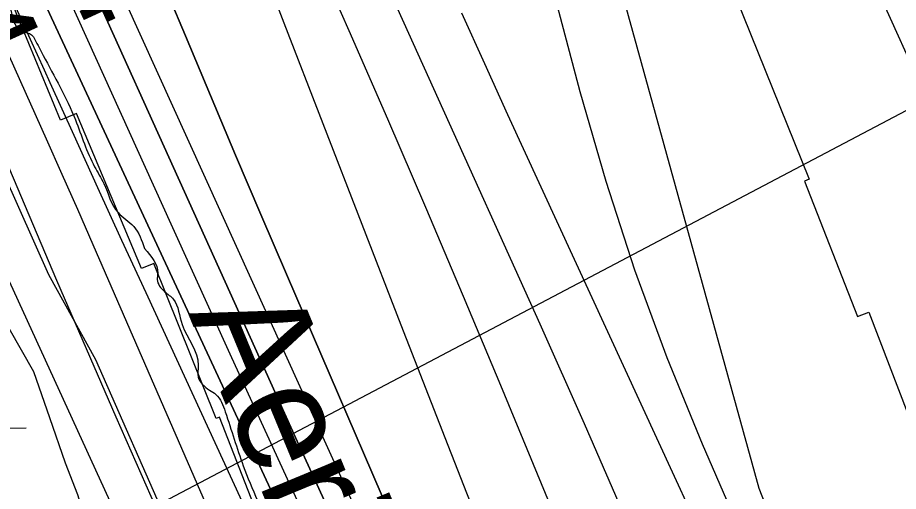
# Model space of a CAD drawing. Extents: x 3424494 to 3462436, y 522220 to 547718.
# Drawn here: x 3439589 to 3440243, y 541201 to 541553 of the extents above; entities that cross this region are included whole.
import ezdxf

# ---------------------------------------------------------------- set-up
doc = ezdxf.new("R2010")
doc.units = 0
for name, color, linetype in [('V-RIVR-EDGE', 7, 'Continuous'), ('V-RIVR-IDEN', 7, 'Continuous'), ('V-RIVR-RANG', 7, 'Continuous'), ('V-RRAP-RVMT', 7, 'Continuous'), ('V-SITE-VEGE', 7, 'Continuous'), ('V-TOPO-DPTH', 7, 'Continuous'), ('V-TOPO-MAJR', 7, 'Continuous'), ('V-TOPO-MINR', 7, 'Continuous'), ('V-TOPO-WATR', 7, 'Continuous'), ('V-WETL-SWMP', 7, 'Continuous')]:
    doc.layers.add(name, color=color, linetype=linetype)

msp = doc.modelspace()

# ---------------------------------------------------------------- linework, layer by layer
at = {"layer": 'V-RIVR-EDGE'}
for points in [[(3438393.42, 545837.57), (3438393.61, 545836.87), (3438395.05, 545831.39), (3438401.62, 545826.62), (3438403.8, 545821.13), (3438403.78, 545813.45), (3438405.22, 545801.75), (3438408.47, 545786.39), (3438409.18, 545777.98), (3438409.16, 545769.94), (3438409.49, 545757.14), (3438410.92, 545744.71), (3438420.29, 545688.76), (3438423.49, 545652.93), (3438428.86, 545606.12), (3438430.6, 545570.3), (3438432.37, 545549.09), (3438435.92, 545504.12), (3438439.16, 545485.47), (3438444.96, 545463.89), (3438449.31, 545451.81), (3438457.7, 545444.12), (3438458.06, 545439), (3438458.77, 545433.15), (3438463.52, 545430.21), (3438470.82, 545426.9), (3438472.63, 545421.41), (3438472.25, 545413.01), (3438471.11, 545394.73), (3438468.15, 545380.85), (3438467.77, 545375.37), (3438465.55, 545364.41), (3438464.78, 545351.25), (3438465.85, 545339.91), (3438471.67, 545328.93), (3438480.75, 545301.86), (3438480.71, 545287.24), (3438482.14, 545273.71), (3438487.22, 545257.98), (3438494.14, 545246.99), (3438498.87, 545239.31), (3438502.86, 545227.23), (3438508.27, 545196.51), (3438511.14, 545174.21), (3438523.44, 545123), (3438525.59, 545104.72), (3438525.57, 545098.14), (3438527.72, 545082.41), (3438530.97, 545064.86), (3438530.94, 545051.33), (3438530.54, 545038.91), (3438527.6, 545030.87), (3438526.84, 545021), (3438528.62, 545002.72), (3438527.46, 544975.67), (3438526.31, 544955.57), (3438524.81, 544938.76), (3438526.99, 544931.81), (3438537.92, 544918.26), (3438543.74, 544908.37), (3438545.55, 544899.23), (3438545.53, 544889.73), (3438542.56, 544875.11), (3438542.17, 544862.68), (3438543.62, 544857.2), (3438543.61, 544855), (3438540.68, 544850.62), (3438539.19, 544841.12), (3438540.25, 544827.23), (3438541.69, 544817.72), (3438544.95, 544805.29), (3438544.91, 544790.3), (3438543.39, 544767.27), (3438545.9, 544746.43), (3438547.7, 544732.9), (3438549.12, 544719.01), (3438553.49, 544712.42), (3438557.51, 544708.38), (3438557.13, 544706.19), (3438556.03, 544704.37), (3438550.91, 544701.46), (3438550.16, 544693.78), (3438554.49, 544672.57), (3438557.73, 544650.63), (3438563.14, 544620.27), (3438569.66, 544598.69), (3438581.95, 544543.1), (3438585.19, 544522.98), (3438584.79, 544506.53), (3438588.41, 544491.17), (3438594.94, 544472.51), (3438598.56, 544458.98), (3438598.51, 544439.6), (3438598.48, 544424.98), (3438598.08, 544411.82), (3438598.06, 544405.61), (3438599.51, 544397.56), (3438604.22, 544381.1), (3438610.37, 544356.96), (3438613.26, 544341.6), (3438619.09, 544333.18), (3438624.91, 544321.1), (3438628.15, 544301.72), (3438628.82, 544279.42), (3438634.99, 544260.03), (3438634.97, 544251.26), (3438637.85, 544233.34), (3438638.54, 544216.16), (3438645.09, 544204.08), (3438650.91, 544193.1), (3438650.88, 544182.13), (3438651.56, 544159.1), (3438651.54, 544153.25), (3438652.96, 544137.53), (3438657.32, 544123.99), (3438667.11, 544092.89), (3438672.9, 544069.49), (3438679.8, 544048.63), (3438680.49, 544035.47), (3438681.93, 544024.5), (3438680.45, 544017.19), (3438685.53, 544000.73), (3438686.94, 543981.72), (3438692.73, 543957.58), (3438693.77, 543933.08), (3438694.09, 543918.1), (3438698.07, 543900.54), (3438698.41, 543889.94), (3438698.4, 543885.55), (3438700.96, 543885.18), (3438708.64, 543887.72), (3438712.65, 543882.59), (3438718.45, 543864.67), (3438733.33, 543818.2), (3438741.31, 543793.69), (3438746.73, 543767.36), (3438753.96, 543734.08), (3438762.28, 543698.96), (3438770.98, 543671.53), (3438780.05, 543642.62), (3438782.94, 543630.92), (3438781.85, 543630.92), (3438771.24, 543630.22), (3438766.85, 543628.77), (3438765.74, 543622.56), (3438771.21, 543615.23), (3438777.02, 543602.42), (3438775.17, 543590), (3438778.8, 543582.31), (3438781.72, 543581.21), (3438785.75, 543582.3), (3438793.07, 543586.3), (3438797.82, 543584.82), (3438800.36, 543578.24), (3438805.76, 543546.06), (3438811.93, 543525.94), (3438819.53, 543497.04), (3438822.81, 543490.09), (3438824.62, 543484.96), (3438830.07, 543471.42), (3438839.89, 543450.93), (3438843.89, 543441.78), (3438850.42, 543423.85), (3438851.87, 543417.27), (3438850.75, 543408.13), (3438850.37, 543400.82), (3438855.08, 543386.19), (3438860.17, 543372.29), (3438866.73, 543366.06), (3438867.8, 543356.55), (3438867.78, 543347.78), (3438868.86, 543341.19), (3438880.52, 543326.91), (3438889.63, 543312.99), (3438898.72, 543293.96), (3438901.98, 543280.06), (3438905.96, 543265.07), (3438917.2, 543229.58), (3438923, 543209.46), (3438927.74, 543203.6), (3438932.81, 543185.68), (3438937.14, 543160.81), (3438942.56, 543134.84), (3438946.9, 543117.65), (3438946.88, 543110.34), (3438946.5, 543102.66), (3438951.23, 543091.69), (3438960.71, 543082.52), (3438961.42, 543076.67), (3438965.41, 543063.87), (3438966.48, 543053.26), (3438963.91, 543047.42), (3438962.07, 543042.67), (3438965.32, 543026.95), (3438970.39, 543005.37), (3438977.28, 542983.78), (3438982.74, 542973.9), (3438991.83, 542954.87), (3439000.92, 542934.01), (3439008.55, 542918.64), (3439023.85, 542895.57), (3439028.21, 542883.13), (3439036.95, 542873.24), (3439040.94, 542860.8), (3439048.21, 542843.6), (3439058.78, 542827.86), (3439070.41, 542802.61), (3439079.5, 542782.84), (3439082.38, 542763.46), (3439082.71, 542749.21), (3439081.58, 542735.32), (3439079.34, 542717.41), (3439078.96, 542710.47), (3439082.94, 542696.93), (3439086.21, 542687.79), (3439090.59, 542683.75), (3439099.36, 542684.1), (3439102.28, 542680.07), (3439104.09, 542676.04), (3439104.07, 542668.37), (3439104.05, 542657.4), (3439105.49, 542647.53), (3439106.2, 542642.04), (3439115.29, 542621.18), (3439129.13, 542598.85), (3439132.42, 542599.57), (3439141.52, 542584.2), (3439147.32, 542566.64), (3439154.59, 542546.88), (3439164.04, 542527.48), (3439169.85, 542510.65), (3439173.48, 542500.04), (3439177.48, 542490.89), (3439190.59, 542472.22), (3439206.25, 542447.32), (3439209.14, 542433.06), (3439211.31, 542426.84), (3439222.26, 542418.41), (3439225.9, 542411.82), (3439227.33, 542401.21), (3439229.88, 542396.09), (3439237.54, 542388.03), (3439240.44, 542378.88), (3439242.98, 542371.2), (3439252.8, 542351.07), (3439262.61, 542326.19), (3439271.71, 542310.81), (3439276.41, 542291.79), (3439280.39, 542275.33), (3439282.56, 542264.73), (3439280.36, 542261.08), (3439278.16, 542259.25), (3439283.24, 542243.89), (3439285.4, 542231.82), (3439293.05, 542221.2), (3439297.05, 542211.69), (3439308.34, 542194.48), (3439310.89, 542190.45), (3439316.37, 542190.07), (3439317.46, 542186.05), (3439322.88, 542161.54), (3439326.86, 542146.18), (3439328.66, 542133.38), (3439327.89, 542118.76), (3439331.14, 542099.74), (3439347.11, 542053.28), (3439351.81, 542035.36), (3439360.55, 542018.88), (3439371.1, 542000.58), (3439381.29, 541982.64), (3439394.06, 541973.11), (3439397.7, 541966.88), (3439399.87, 541955.55), (3439406.05, 541943.47), (3439414.79, 541930.65), (3439422.81, 541920.76), (3439437.76, 541904.64), (3439450.5, 541882.31), (3439460.66, 541852.68), (3439464.66, 541843.89), (3439468.29, 541833.28), (3439481.77, 541815.34), (3439490.14, 541800.7), (3439498.52, 541788.61), (3439505.07, 541778.36), (3439505.42, 541771.41), (3439505.75, 541754.6), (3439506.83, 541747.65), (3439515.2, 541733.74), (3439522.83, 541717.27), (3439531.22, 541708.84), (3439533.76, 541701.16), (3439533.73, 541689.83), (3439534.05, 541670.45), (3439534.03, 541662.04), (3439535.48, 541656.56), (3439543.49, 541645.21), (3439555.87, 541625.8), (3439565.7, 541607.5), (3439574.05, 541583.72), (3439582.77, 541562.5), (3439587.48, 541546.4), (3439591.86, 541542.73), (3439598.8, 541540.16), (3439601.35, 541536.5), (3439607.53, 541524.78), (3439631.54, 541476.84), (3439645.71, 541442.07), (3439652.62, 541429.63), (3439663.17, 541408.03), (3439674.84, 541397.77), (3439682.85, 541381.3)], [(3439682.85, 541381.3), (3439692.67, 541363), (3439692.29, 541358.25), (3439697.75, 541349.46), (3439704.32, 541343.6), (3439710.85, 541324.94), (3439722.84, 541294.57), (3439722.82, 541285.79), (3439731.2, 541276.27), (3439735.95, 541272.97), (3439742.86, 541260.16), (3439756.29, 541219.91), (3439766.82, 541194.3), (3439775.91, 541174.17), (3439786.46, 541150.38), (3439790.06, 541130.27), (3439793.67, 541111.25), (3439796.96, 541109.42), (3439800.23, 541105.02), (3439803.86, 541094.78), (3439809.31, 541080.51), (3439814.75, 541062.22), (3439818.38, 541050.14), (3439827.49, 541039.52), (3439836.22, 541023.42), (3439840.93, 541006.59), (3439841.28, 540998.18), (3439847.09, 540982.45), (3439853.63, 540968.54), (3439860.54, 540953.17), (3439866.72, 540938.17), (3439870.34, 540926.46), (3439873.63, 540926.45), (3439879.48, 540924.61), (3439882.02, 540918.75), (3439885.64, 540902.3), (3439892.54, 540885.1), (3439899.8, 540865.71), (3439911.44, 540842.65), (3439935.1, 540800.92), (3439941.28, 540788.47), (3439946.73, 540774.57), (3439954, 540757), (3439968.56, 540730.28), (3439989.29, 540687.1), (3440003.47, 540658.18), (3440015.84, 540633.3), (3440027.11, 540609.14), (3440035.83, 540588.65), (3440041.29, 540576.57), (3440055.13, 540558.26), (3440061.33, 540549.47), (3440068.61, 540540.32), (3440073.34, 540530.43), (3440079.52, 540516.16), (3440083.5, 540498.61), (3440091.08, 540461.67), (3440099.4, 540424), (3440109.55, 540389.24), (3440130.58, 540320.1), (3440139.28, 540291.2), (3440148.01, 540272.54), (3440154.55, 540259.73), (3440159.28, 540248.02), (3440163.64, 540239.6), (3440170.93, 540227.88), (3440200.42, 540183.21), (3440216.44, 540154.66), (3440238.66, 540121.71), (3440247.39, 540107.06), (3440254.68, 540096.08), (3440271.8, 540071.91), (3440285.29, 540057.26)]]:
    msp.add_spline(points, degree=3, dxfattribs=at)
at = {"layer": 'V-RIVR-RANG'}
msp.add_line((3439472.4, 541075.21), (3440375.08, 541550.15), dxfattribs=at)
at = {"layer": 'V-RRAP-RVMT'}
for p, q in [((3439620.44, 541476.79), (3439574.23, 541588.12)), ((3440120.69, 541572.65), (3440177.07, 541432.82)), ((3439632.28, 541481.7), (3439620.44, 541476.79)), ((3439680.73, 541366.41), (3439632.28, 541481.7)), ((3440177.07, 541432.82), (3440173.63, 541431.43)), ((3440173.63, 541431.43), (3440213.07, 541330.86)), ((3439689.77, 541370.18), (3439680.73, 541366.41)), ((3439736.24, 541255.09), (3439689.77, 541370.18)), ((3440213.07, 541330.86), (3440221.36, 541334.06)), ((3440221.36, 541334.06), (3440271.39, 541203.68)), ((3439738.62, 541256.05), (3439736.24, 541255.09)), ((3439775.22, 541162.81), (3439738.62, 541256.05))]:
    msp.add_line(p, q, dxfattribs=at)
at = {"layer": 'V-SITE-VEGE'}
msp.add_lwpolyline([(3439578.02, 541437.11), (3439611.39, 541362.1), (3439646.5, 541299.03), (3439701.29, 541174.7), (3439734.35, 541109.18), (3439748.69, 541054.51), (3439762.6, 541003.85), (3439770.08, 540979.75), (3439781.83, 540944.6), (3439798.79, 540896.36), (3439831.77, 540826.85), (3439859.89, 540763.42)], dxfattribs=at)
at = {"layer": 'V-TOPO-DPTH'}
for points in [[(3439750.53, 541450.72), (3439731.83, 541494.97), (3439713.23, 541539.26), (3439689.15, 541596.86), (3439682.65, 541612.38), (3439676.12, 541627.88), (3439669.57, 541643.38), (3439662.99, 541658.86), (3439571.38, 541873.92)], [(3439750.53, 541450.72), (3439731.83, 541494.97), (3439713.23, 541539.26), (3439689.15, 541596.86), (3439682.65, 541612.38), (3439676.12, 541627.88), (3439669.57, 541643.38), (3439662.99, 541658.86), (3439571.38, 541873.92)], [(3440491.9, 540111.27), (3440123.75, 540846.97), (3440121.77, 540851.91), (3440119.88, 540856.88), (3440118.05, 540861.87), (3440113.71, 540874.02), (3440109.7, 540885.08), (3440105.6, 540896.11), (3440101.38, 540907.09), (3440097.07, 540918.05), (3440093.61, 540926.72), (3440087.48, 540941.97), (3440081.32, 540957.21), (3440075.09, 540972.42), (3440068.83, 540987.62), (3439947.77, 541279.74), (3439920.11, 541345.81), (3439892.15, 541411.75), (3439863.72, 541477.49), (3439834.98, 541543.11), (3439795.07, 541633.34)], [(3440491.9, 540111.27), (3440123.75, 540846.97), (3440121.77, 540851.91), (3440119.88, 540856.88), (3440118.05, 540861.87), (3440113.71, 540874.02), (3440109.7, 540885.08), (3440105.6, 540896.11), (3440101.38, 540907.09), (3440097.07, 540918.05), (3440093.61, 540926.72), (3440087.48, 540941.97), (3440081.32, 540957.21), (3440075.09, 540972.42), (3440068.83, 540987.62), (3439947.77, 541279.74), (3439920.11, 541345.81), (3439892.15, 541411.75), (3439863.72, 541477.49), (3439834.98, 541543.11), (3439795.07, 541633.34)], [(3439587.71, 541608.96), (3439970.51, 540785.55), (3440067.12, 540601.4), (3440170.5, 540405.32), (3440401.09, 540001.18), (3440433.34, 539960.23), (3440699.8, 539603.68)], [(3440699.8, 539603.68), (3440433.34, 539960.23), (3440401.09, 540001.18), (3440170.5, 540405.32), (3440067.12, 540601.4), (3439970.51, 540785.55), (3439587.71, 541608.96)], [(3439636.98, 541590.89), (3439795.13, 541241.12), (3439829.72, 541165.29), (3439864.63, 541089.61), (3439900.04, 541014.16), (3439935.79, 540938.87), (3439990.09, 540825.43), (3439999.04, 540807.03), (3440008.13, 540788.71), (3440017.45, 540770.49)], [(3440017.45, 540770.49), (3440008.13, 540788.71), (3439999.04, 540807.03), (3439990.09, 540825.43), (3439935.79, 540938.87), (3439900.04, 541014.16), (3439864.63, 541089.61), (3439829.72, 541165.29), (3439795.13, 541241.12), (3439636.98, 541590.89)], [(3439781.45, 541561.71), (3439786.45, 541548.91), (3439873.47, 541324.59), (3439906.09, 541241.03), (3439938.94, 541157.57), (3439972.14, 541074.25), (3440005.58, 540991.02), (3440047.9, 540886.34), (3440060.63, 540855.64), (3440073.73, 540825.1), (3440370.4, 540258.45), (3440416.28, 540175.83), (3440427.99, 540155.09), (3440439.9, 540134.46), (3440452.12, 540114.02), (3440464.53, 540093.69), (3440484.52, 540061.49), (3440487.14, 540057.38), (3440489.82, 540053.32), (3440492.6, 540049.33), (3440495.45, 540045.37), (3440671.07, 539807.54), (3440730.42, 539727.92), (3440790.25, 539648.66)], [(3439781.45, 541561.71), (3439786.45, 541548.91), (3439873.47, 541324.59), (3439906.09, 541241.03), (3439938.94, 541157.57), (3439972.14, 541074.25), (3440005.58, 540991.02), (3440047.9, 540886.34), (3440060.63, 540855.64), (3440073.73, 540825.1), (3440370.4, 540258.45), (3440416.28, 540175.83), (3440427.99, 540155.09), (3440439.9, 540134.46), (3440452.12, 540114.02), (3440464.53, 540093.69), (3440484.52, 540061.49), (3440487.14, 540057.38), (3440489.82, 540053.32), (3440492.6, 540049.33), (3440495.45, 540045.37), (3440671.07, 539807.54), (3440730.42, 539727.92), (3440790.25, 539648.66)], [(3439582.31, 541524.08), (3439598.19, 541488.82), (3439609.86, 541462.77), (3439621.47, 541436.69), (3439632.98, 541410.57), (3439644.43, 541384.42), (3439785.43, 541060.77), (3439808.81, 541007.88), (3439832.56, 540955.17), (3439856.89, 540902.72), (3439881.59, 540850.44), (3439919.41, 540771.5)], [(3440231.78, 540444.09), (3440040.37, 540797.56), (3440038.5, 540801.07), (3440036.65, 540804.58), (3440034.85, 540808.12), (3440033.07, 540811.67), (3440020.69, 540836.74), (3440012.83, 540852.88), (3440005.09, 540869.07), (3439997.52, 540885.35), (3439990.07, 540901.68), (3439959.97, 540968.61), (3439937.67, 541018.5), (3439915.53, 541068.46), (3439893.62, 541118.52), (3439871.87, 541168.65), (3439788.33, 541362.39), (3439769.38, 541406.54), (3439750.53, 541450.72)], [(3440231.78, 540444.09), (3440040.37, 540797.56), (3440038.5, 540801.07), (3440036.65, 540804.58), (3440034.85, 540808.12), (3440033.07, 540811.67), (3440020.69, 540836.74), (3440012.83, 540852.88), (3440005.09, 540869.07), (3439997.52, 540885.35), (3439990.07, 540901.68), (3439959.97, 540968.61), (3439937.67, 541018.5), (3439915.53, 541068.46), (3439893.62, 541118.52), (3439871.87, 541168.65), (3439788.33, 541362.39), (3439769.38, 541406.54), (3439750.53, 541450.72)]]:
    msp.add_lwpolyline(points, dxfattribs=at)
at = {"layer": 'V-TOPO-MAJR'}
msp.add_lwpolyline([(3440844.74, 539671.38), (3440819.62, 539704.83), (3440794.5, 539738.29), (3440769.41, 539771.76), (3440744.32, 539805.25), (3440719.34, 539838.81), (3440694.47, 539872.45), (3440669.77, 539906.21), (3440645.19, 539940.07), (3440568.78, 540045.86), (3440554.46, 540066.25), (3440540.53, 540086.9), (3440527.16, 540107.91), (3440514.17, 540129.17), (3440158.46, 540895.38), (3440151.02, 540914.21), (3440105.04, 541027), (3440073.99, 541101.97), (3440042.38, 541176.71), (3440009.94, 541251.08), (3439976.95, 541325.22), (3439819.03, 541674.84)], dxfattribs=at)
at = {"layer": 'V-TOPO-MINR'}
for points in [[(3439571.38, 541873.92), (3439662.99, 541658.86), (3439669.57, 541643.38), (3439676.12, 541627.88), (3439682.65, 541612.38), (3439689.15, 541596.86), (3439713.23, 541539.26), (3439731.83, 541494.97), (3439750.53, 541450.72)], [(3439991.92, 541737.33), (3440139.58, 541203.45), (3440152.53, 541170.38), (3440239.52, 540967.78), (3440248.24, 540947.45), (3440256.96, 540927.12), (3440265.66, 540906.78), (3440274.36, 540886.44), (3440576.19, 540114.85), (3440577.19, 540113.35), (3440579.32, 540110.45), (3440580.44, 540109.04), (3441329.18, 539161.01)], [(3440491.9, 540111.27), (3440123.75, 540846.97), (3440121.77, 540851.91), (3440119.88, 540856.88), (3440118.05, 540861.87), (3440113.71, 540874.02), (3440109.7, 540885.08), (3440105.6, 540896.11), (3440101.38, 540907.09), (3440097.07, 540918.05), (3440093.61, 540926.72), (3440087.48, 540941.97), (3440081.32, 540957.21), (3440075.09, 540972.42), (3440068.83, 540987.62), (3439947.77, 541279.74), (3439920.11, 541345.81), (3439892.15, 541411.75), (3439863.72, 541477.49), (3439834.98, 541543.11), (3439795.07, 541633.34)], [(3439975, 541617.02), (3440006.55, 541497.95), (3440025.83, 541431.33), (3440047.1, 541365.41), (3440071.33, 541300.52), (3440097.56, 541236.32), (3440228.45, 540935.59), (3440232.69, 540925.79), (3440236.91, 540915.97), (3440241.09, 540906.15), (3440245.24, 540896.31), (3440265.1, 540848.96), (3440278.76, 540815.28), (3440291.86, 540781.4), (3440304.15, 540747.22), (3440315.9, 540712.83), (3440562.18, 540117.77), (3440566, 540112.05), (3440569.94, 540106.4), (3440574.03, 540100.87), (3440578.24, 540095.42), (3440836.01, 539771.54), (3440998.13, 539561.63)], [(3439467.12, 541608.45), (3439865.64, 540738.35), (3439871.13, 540726.96), (3439876.71, 540715.62), (3439882.42, 540704.34), (3439888.22, 540693.11), (3439894.09, 540681.91), (3439899.95, 540670.71), (3439905.8, 540659.5), (3439911.66, 540648.3), (3439920.87, 540630.68), (3439920.57, 540624.57), (3439918.65, 540620.57), (3439914.29, 540619.72), (3439908.31, 540620.97), (3439863.09, 540661.94), (3439847.45, 540676.37), (3439832.01, 540690.99), (3439816.84, 540705.9), (3439802.56, 540720.29)], [(3439656.24, 541591.86), (3439892.9, 541070.5), (3439913.95, 541024.61), (3439935.23, 540978.84), (3439956.87, 540933.23), (3439978.75, 540887.74), (3440012.52, 540818.19), (3440017.75, 540807.58), (3440023.06, 540797.02), (3440028.5, 540786.52), (3440034.02, 540776.06)], [(3439636.98, 541590.89), (3439795.13, 541241.12), (3439829.72, 541165.29), (3439864.63, 541089.61), (3439900.04, 541014.16), (3439935.79, 540938.87), (3439990.09, 540825.43), (3439999.04, 540807.03), (3440008.13, 540788.71), (3440017.45, 540770.49)], [(3440641.24, 540727.97), (3440474.33, 541036.16), (3440471.34, 541041.74), (3440468.4, 541047.35), (3440465.51, 541052.98), (3440462.67, 541058.64), (3440443.43, 541097.4), (3440431.16, 541122.53), (3440419.11, 541147.75), (3440407.37, 541173.13), (3440395.85, 541198.61), (3440353.07, 541294.85), (3440320.23, 541368.48), (3440287.26, 541442.05), (3440254.1, 541515.54), (3440220.81, 541588.97)], [(3439577.33, 541582.6), (3439592.76, 541548.26), (3439608.26, 541513.95), (3439612.53, 541504.53), (3439630.26, 541465.55), (3439648.04, 541426.59), (3439665.88, 541387.66), (3439683.76, 541348.76), (3439934.9, 540803.63), (3439937.74, 540797.46), (3439940.57, 540791.29), (3439943.39, 540785.11), (3439946.2, 540778.93)], [(3439627.45, 541565.4), (3439702.4, 541399.73), (3439747.65, 541300.37), (3439793.22, 541201.16), (3439839.28, 541102.17), (3439885.67, 541003.34), (3439965.97, 540833.34), (3439978.86, 540806.47), (3439991.98, 540779.71)], [(3439781.45, 541561.71), (3439786.45, 541548.91), (3439873.47, 541324.59), (3439906.09, 541241.03), (3439938.94, 541157.57), (3439972.14, 541074.25), (3440005.58, 540991.02), (3440047.9, 540886.34), (3440060.63, 540855.64), (3440073.73, 540825.1), (3440370.4, 540258.45), (3440416.28, 540175.83), (3440427.99, 540155.09), (3440439.9, 540134.46), (3440452.12, 540114.02), (3440464.53, 540093.69), (3440484.52, 540061.49), (3440487.14, 540057.38), (3440489.82, 540053.32), (3440492.6, 540049.33), (3440495.45, 540045.37), (3440671.07, 539807.54), (3440730.42, 539727.92), (3440790.25, 539648.66)], [(3439918.43, 541556.47), (3439935.56, 541518.7), (3439952.83, 541480.99), (3440212.14, 540918.36), (3440213.04, 540916.42), (3440214.85, 540912.55), (3440215.76, 540910.61), (3440217.44, 540907.05), (3440217.93, 540905.79), (3440218.14, 540905.15), (3440218.24, 540904.83), (3440542.86, 540122.1), (3440550.46, 540110.31), (3440558.27, 540098.67), (3440566.39, 540087.25), (3440574.72, 540075.96), (3440740.26, 539857.93), (3440780.12, 539805.26), (3440819.86, 539752.49), (3440859.43, 539699.6), (3440898.88, 539646.62)], [(3439541.14, 541537.21), (3439617.5, 541357.82), (3439661.43, 541256.35), (3439706.19, 541155.26), (3439752.19, 541054.72), (3439799.02, 540954.56), (3439879.95, 540784.21), (3439892.66, 540757.88)], [(3439582.31, 541524.08), (3439598.19, 541488.82), (3439609.86, 541462.77), (3439621.47, 541436.69), (3439632.98, 541410.57), (3439644.43, 541384.42), (3439785.43, 541060.77), (3439808.81, 541007.88), (3439832.56, 540955.17), (3439856.89, 540902.72), (3439881.59, 540850.44), (3439919.41, 540771.5)], [(3439750.53, 541450.72), (3439769.38, 541406.54), (3439788.33, 541362.39), (3439871.87, 541168.65), (3439893.62, 541118.52), (3439915.53, 541068.46), (3439937.67, 541018.5), (3439959.97, 540968.61), (3439990.07, 540901.68), (3439997.52, 540885.35), (3440005.09, 540869.07), (3440012.83, 540852.88), (3440020.69, 540836.74), (3440033.07, 540811.67), (3440034.85, 540808.12), (3440036.65, 540804.58), (3440038.5, 540801.07), (3440040.37, 540797.56), (3440231.78, 540444.09)]]:
    msp.add_lwpolyline(points, dxfattribs=at)
at = {"layer": 'V-TOPO-WATR'}
msp.add_lwpolyline([(3440699.8, 539603.68), (3440433.34, 539960.23), (3440401.09, 540001.18), (3440170.5, 540405.32), (3440067.12, 540601.4), (3439970.51, 540785.55), (3439587.71, 541608.96)], dxfattribs=at)
at = {"layer": 'V-WETL-SWMP'}
msp.add_line((3439523.48, 541247.84), (3439594.9, 541248.16), dxfattribs=at)
msp.add_lwpolyline([(3439582.11, 541322.3), (3439600.28, 541289.91), (3439612.13, 541255.75), (3439624, 541222.23), (3439632.93, 541198.81), (3439639.4, 541177.33), (3439646.37, 541150.19), (3439660, 541110.97), (3439671.29, 541079.97), (3439671.91, 541079.33), (3439688.09, 541041.95), (3439699.52, 541017.85), (3439710.39, 540996.91), (3439725.27, 540957.04), (3439741.54, 540924.06), (3439757.17, 540890.45), (3439766.27, 540875.2), (3439775.43, 540862.45), (3439787.91, 540828.28), (3439800.89, 540787.83), (3439813.89, 540748.63)], dxfattribs=at)

# ---------------------------------------------------------------- texts
at = {"layer": 'V-RIVR-IDEN'}
msp.add_text('Aerial ', height=83, rotation=292.50573, dxfattribs=at).set_placement((3439715.1, 541333.29))
at = {"layer": 'V-RIVR-RANG'}
for s, rotation, p in [('12.4', 294.47833, (3439475.01, 541666.37)), ('-14', 294.76308, (3439588.21, 541658.3))]:
    msp.add_text(s, height=67, rotation=rotation, dxfattribs=at).set_placement(p)

doc.saveas('drawing.dxf')
